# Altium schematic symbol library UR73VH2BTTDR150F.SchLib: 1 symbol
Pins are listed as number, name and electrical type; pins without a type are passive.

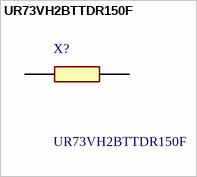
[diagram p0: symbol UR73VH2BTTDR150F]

## UR73VH2BTTDR150F
designator X?
Current Sense Resistors - SMD 1206 1W 0.15ohm 1% AEC-Q200; Manufacturer_Name: KOA Speer; Geometry.Height: 0.7mm
footprint RESC3216X70N
pins: 1, 2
